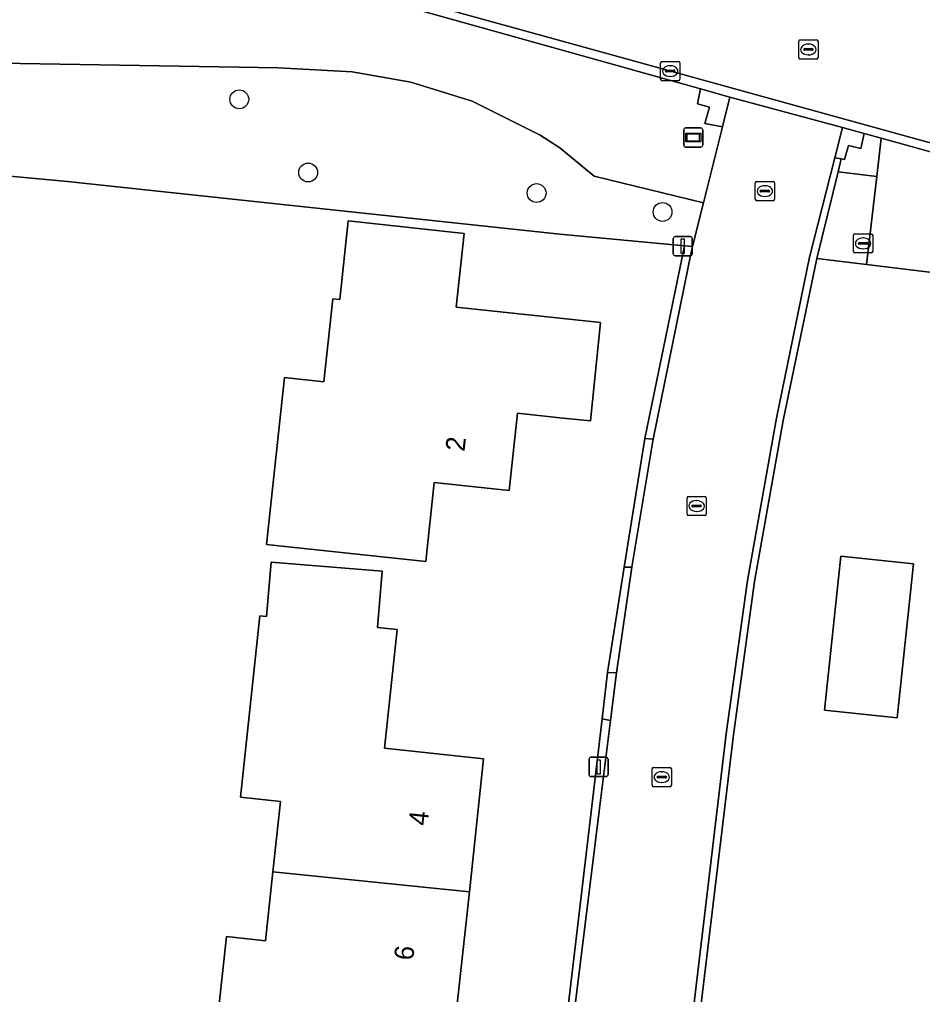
# Model space of a CAD drawing. Extents: x 162156 to 163172, y 378995 to 380779.
# Drawn here: x 162471.9 to 162518.8, y 380585.7 to 380636.4 of the extents above; entities that cross this region are included whole.
import ezdxf

# ---------------------------------------------------------------- set-up
doc = ezdxf.new("R2010")
doc.units = 0
for name, color, linetype in [('IMGEO_Boom', 7, 'Continuous'), ('IMGEO_Brandkraan', 7, 'Continuous'), ('IMGEO_Erf', 7, 'Continuous'), ('IMGEO_Groenvoorziening', 7, 'Continuous'), ('IMGEO_Kolk', 7, 'Continuous'), ('IMGEO_Lichtmast', 7, 'Continuous'), ('IMGEO_Pand', 7, 'Continuous'), ('IMGEO_Pand_nummerreeks', 7, 'Continuous'), ('IMGEO_Rijbaan_lokaal_gesloten', 7, 'Continuous'), ('IMGEO_Rijbaan_lokaal_open', 7, 'Continuous'), ('IMGEO_Rioolput', 7, 'Continuous'), ('IMGEO_Straatnaambord', 7, 'Continuous'), ('IMGEO_Voetpad_open', 7, 'Continuous')]:
    doc.layers.add(name, color=color, linetype=linetype)

msp = doc.modelspace()

# ---------------------------------------------------------------- linework, layer by layer
at = {"layer": 'IMGEO_Boom'}
for centre in [(162483.344, 380632.211), (162486.919, 380628.409), (162498.79, 380627.343), (162505.335, 380626.359)]:
    msp.add_circle(centre, 0.489, dxfattribs=at)
at = {"layer": 'IMGEO_Brandkraan'}
for p, q in [((162515.325, 380625.227), (162516.177, 380625.227)), ((162515.25, 380624.301), (162515.25, 380625.153)), ((162515.509, 380624.721), (162515.509, 380624.733)), ((162515.552, 380624.77), (162515.95, 380624.77)), ((162515.738, 380625.007), (162515.763, 380625.007)), ((162515.993, 380624.733), (162515.993, 380624.721)), ((162516.251, 380625.153), (162516.251, 380624.301)), ((162516.177, 380624.227), (162515.325, 380624.227)), ((162515.947, 380624.684), (162515.549, 380624.684)), ((162515.761, 380624.447), (162515.736, 380624.447))]:
    msp.add_line(p, q, dxfattribs=at)
for points in [[(162515.325, 380625.227), (162516.177, 380625.227)], [(162515.25, 380624.301), (162515.25, 380625.153)], [(162516.251, 380625.153), (162516.251, 380624.301)], [(162516.177, 380624.227), (162515.325, 380624.227)]]:
    msp.add_lwpolyline(points, dxfattribs=at)
for centre, radius, start, end in [((162515.327, 380625.151), 0.0765, 91.552, 178.448), ((162515.327, 380625.151), 0.0765, 91.552, 178.448), ((162516.175, 380625.151), 0.0765, 1.552, 88.448), ((162516.175, 380625.151), 0.0765, 1.552, 88.448), ((162515.549, 380624.73), 0.0403, 85.8775, 175.7526), ((162515.546, 380624.72), 0.0366, 178.938, 274.7102), ((162515.95, 380624.727), 0.043, 264.8664, 352.4533), ((162515.954, 380624.732), 0.0386, 1.7309, 96.639), ((162515.327, 380624.303), 0.0765, 181.552, 268.448), ((162515.327, 380624.303), 0.0765, 181.552, 268.448), ((162516.175, 380624.303), 0.0765, 271.552, 358.448), ((162516.175, 380624.303), 0.0765, 271.552, 358.448)]:
    msp.add_arc(centre, radius, start, end, dxfattribs=at)
for centre, major_axis, ratio, start_param, end_param in [((162515.737, 380624.727), (-0.387, 0.002), 0.722429, 4.712389, 7.853982), ((162515.762, 380624.727), (-0.39, 0.002), 0.717154, 1.570796, 4.712389)]:
    msp.add_ellipse(centre, major_axis=major_axis, ratio=ratio, start_param=start_param, end_param=end_param, dxfattribs=at)
at = {"layer": 'IMGEO_Erf'}
for points in [[(162502.189, 380600.029), (162502.472, 380602.43), (162503.344, 380607.897), (162504.412, 380614.587), (162506.479, 380624.601), (162500, 380625.199), (162474.413, 380627.947), (162438.013, 380631.313), (162439.468, 380615.71), (162440.015, 380601.307), (162439.768, 380588.845), (162437.05, 380560.078), (162436.315, 380552.915), (162465.464, 380549.639), (162490.566, 380547.063), (162491.852, 380559.491), (162500, 380564.632), (162501.13, 380565.345), (162499.992, 380567.526)], [(162613.014, 380601.728), (162588.761, 380608.641), (162562.907, 380615.723), (162561.588, 380616.076), (162561.281, 380614.93), (162560.907, 380613.778), (162560.551, 380612.977), (162560.107, 380612.313), (162544.999, 380616.712), (162537.976, 380618.182), (162519.769, 380623.159), (162515.938, 380623.63), (162513.343, 380623.949), (162511.606, 380615.531), (162510.109, 380607.162), (162509.012, 380599.183), (162505.8, 380572.406)], [(162499.104, 380574.108), (162499.208, 380574.957), (162499.508, 380577.409), (162499.584, 380578.026), (162500, 380581.422), (162502.189, 380600.029)]]:
    msp.add_lwpolyline(points, dxfattribs=at)
for points in [[(162485.685, 380617.752), (162487.743, 380617.531), (162488.208, 380621.852), (162488.56, 380621.814), (162489, 380625.896), (162495.03, 380625.247), (162494.616, 380621.403), (162500, 380620.836), (162502.118, 380620.613), (162501.586, 380615.506), (162500, 380615.669), (162497.794, 380615.896), (162497.362, 380611.883), (162493.475, 380612.302), (162493.033, 380608.196), (162484.752, 380609.088)], [(162481.674, 380579.453), (162482.671, 380588.712), (162484.697, 380588.494), (162485.082, 380592.069), (162485.476, 380595.729), (162483.408, 380595.952), (162484.419, 380605.366), (162484.765, 380605.338), (162484.995, 380608.169), (162490.766, 380607.701), (162490.528, 380604.766), (162491.55, 380604.656), (162490.887, 380598.495), (162496.039, 380597.94), (162495.295, 380591.027), (162494.532, 380583.945), (162489.336, 380584.504), (162488.71, 380578.696), (162488.27, 380574.611), (162481.234, 380575.368)], [(162517.515, 380600.073), (162513.752, 380600.472), (162514.6, 380608.468), (162518.363, 380608.069)]]:
    msp.add_lwpolyline(points, close=True, dxfattribs=at)
at = {"layer": 'IMGEO_Groenvoorziening'}
msp.add_lwpolyline([(162465.547, 380639.847), (162452.609, 380638.519), (162438.317, 380637.334), (162438.521, 380635.944), (162437.595, 380635.83), (162437.854, 380633.025), (162463.991, 380631.774), (162466.779, 380634.155), (162485.377, 380633.853), (162489.211, 380633.646), (162492.259, 380633.107), (162495.434, 380632.111), (162498.979, 380630.341), (162500, 380629.686), (162501.777, 380628.214), (162507.464, 380626.838), (162508.449, 380630.789), (162507.522, 380630.962), (162507.766, 380631.808), (162507.151, 380631.978), (162507.306, 380632.754), (162500, 380634.796), (162491.138, 380637.273)], dxfattribs=at)
for points in [[(162507.464, 380626.838), (162501.777, 380628.214), (162500, 380629.686), (162498.979, 380630.341), (162495.434, 380632.111), (162492.259, 380633.107), (162489.211, 380633.646), (162485.377, 380633.853), (162466.779, 380634.155), (162463.991, 380631.774), (162437.854, 380633.025), (162438.013, 380631.313), (162474.413, 380627.947), (162500, 380625.199), (162506.479, 380624.601), (162506.896, 380624.563)], [(162516.692, 380630.19), (162515.816, 380630.433), (162515.633, 380629.66), (162514.99, 380629.805), (162514.784, 380629.087), (162514.62, 380629.116), (162514.451, 380628.435), (162516.464, 380628.204)], [(162515.938, 380623.63), (162516.464, 380628.204), (162514.451, 380628.435), (162513.343, 380623.949)]]:
    msp.add_lwpolyline(points, close=True, dxfattribs=at)
at = {"layer": 'IMGEO_Kolk'}
for p, q in [((162505.233, 380633.253), (162505.233, 380634.105)), ((162505.308, 380634.179), (162506.16, 380634.179)), ((162505.721, 380633.959), (162505.746, 380633.959)), ((162506.234, 380634.105), (162506.234, 380633.253)), ((162505.492, 380633.673), (162505.492, 380633.685)), ((162505.93, 380633.636), (162505.532, 380633.636)), ((162505.535, 380633.722), (162505.933, 380633.722)), ((162505.744, 380633.399), (162505.719, 380633.399)), ((162505.976, 380633.685), (162505.976, 380633.673)), ((162506.16, 380633.179), (162505.308, 380633.179)), ((162510.149, 380627.016), (162510.149, 380627.868)), ((162510.224, 380627.942), (162511.076, 380627.942)), ((162511.15, 380627.868), (162511.15, 380627.016)), ((162510.408, 380627.436), (162510.408, 380627.448)), ((162510.846, 380627.399), (162510.448, 380627.399)), ((162510.451, 380627.485), (162510.849, 380627.485)), ((162510.637, 380627.722), (162510.662, 380627.722)), ((162510.892, 380627.448), (162510.892, 380627.436)), ((162511.076, 380626.942), (162510.224, 380626.942)), ((162510.66, 380627.162), (162510.635, 380627.162)), ((162506.679, 380611.58), (162507.531, 380611.58)), ((162506.604, 380610.654), (162506.604, 380611.506)), ((162506.863, 380611.074), (162506.863, 380611.086)), ((162507.301, 380611.037), (162506.903, 380611.037)), ((162506.906, 380611.123), (162507.304, 380611.123)), ((162507.092, 380611.36), (162507.117, 380611.36)), ((162507.347, 380611.086), (162507.347, 380611.074)), ((162507.605, 380611.506), (162507.605, 380610.654)), ((162507.531, 380610.58), (162506.679, 380610.58)), ((162507.115, 380610.8), (162507.09, 380610.8)), ((162504.792, 380596.567), (162504.792, 380597.419)), ((162504.867, 380597.493), (162505.719, 380597.493)), ((162505.793, 380597.419), (162505.793, 380596.567)), ((162505.051, 380596.987), (162505.051, 380596.999)), ((162505.489, 380596.95), (162505.091, 380596.95)), ((162505.094, 380597.036), (162505.492, 380597.036)), ((162505.28, 380597.273), (162505.305, 380597.273)), ((162505.535, 380596.999), (162505.535, 380596.987)), ((162505.719, 380596.493), (162504.867, 380596.493)), ((162505.303, 380596.713), (162505.278, 380596.713))]:
    msp.add_line(p, q, dxfattribs=at)
for points in [[(162505.233, 380633.253), (162505.233, 380634.105)], [(162505.308, 380634.179), (162506.16, 380634.179)], [(162506.234, 380634.105), (162506.234, 380633.253)], [(162506.16, 380633.179), (162505.308, 380633.179)], [(162510.149, 380627.016), (162510.149, 380627.868)], [(162510.224, 380627.942), (162511.076, 380627.942)], [(162511.15, 380627.868), (162511.15, 380627.016)], [(162511.076, 380626.942), (162510.224, 380626.942)], [(162506.679, 380611.58), (162507.531, 380611.58)], [(162506.604, 380610.654), (162506.604, 380611.506)], [(162507.605, 380611.506), (162507.605, 380610.654)], [(162507.531, 380610.58), (162506.679, 380610.58)], [(162504.792, 380596.567), (162504.792, 380597.419)], [(162504.867, 380597.493), (162505.719, 380597.493)], [(162505.793, 380597.419), (162505.793, 380596.567)], [(162505.719, 380596.493), (162504.867, 380596.493)]]:
    msp.add_lwpolyline(points, dxfattribs=at)
for centre, radius, start, end in [((162505.31, 380634.103), 0.0765, 91.552, 178.448), ((162505.31, 380634.103), 0.0765, 91.552, 178.448), ((162506.158, 380634.103), 0.0765, 1.552, 88.448), ((162506.158, 380634.103), 0.0765, 1.552, 88.448), ((162505.532, 380633.682), 0.0403, 85.8775, 175.7526), ((162505.529, 380633.672), 0.0366, 178.938, 274.7102), ((162505.933, 380633.679), 0.043, 264.8664, 352.4533), ((162505.937, 380633.684), 0.0386, 1.7309, 96.639), ((162505.31, 380633.255), 0.0765, 181.552, 268.448), ((162505.31, 380633.255), 0.0765, 181.552, 268.448), ((162506.158, 380633.255), 0.0765, 271.552, 358.448), ((162506.158, 380633.255), 0.0765, 271.552, 358.448), ((162510.226, 380627.866), 0.0765, 91.552, 178.448), ((162510.226, 380627.866), 0.0765, 91.552, 178.448), ((162511.074, 380627.866), 0.0765, 1.552, 88.448), ((162511.074, 380627.866), 0.0765, 1.552, 88.448), ((162510.448, 380627.445), 0.0403, 85.8775, 175.7526), ((162510.445, 380627.435), 0.0366, 178.938, 274.7102), ((162510.849, 380627.442), 0.043, 264.8664, 352.4533), ((162510.853, 380627.447), 0.0386, 1.7309, 96.639), ((162510.226, 380627.018), 0.0765, 181.552, 268.448), ((162510.226, 380627.018), 0.0765, 181.552, 268.448), ((162511.074, 380627.018), 0.0765, 271.552, 358.448), ((162511.074, 380627.018), 0.0765, 271.552, 358.448), ((162506.681, 380611.504), 0.0765, 91.552, 178.448), ((162506.681, 380611.504), 0.0765, 91.552, 178.448), ((162507.529, 380611.504), 0.0765, 1.552, 88.448), ((162507.529, 380611.504), 0.0765, 1.552, 88.448), ((162506.903, 380611.083), 0.0403, 85.8775, 175.7526), ((162506.9, 380611.073), 0.0366, 178.938, 274.7102), ((162507.304, 380611.08), 0.043, 264.8664, 352.4533), ((162507.308, 380611.085), 0.0386, 1.7309, 96.639), ((162506.681, 380610.656), 0.0765, 181.552, 268.448), ((162506.681, 380610.656), 0.0765, 181.552, 268.448), ((162507.529, 380610.656), 0.0765, 271.552, 358.448), ((162507.529, 380610.656), 0.0765, 271.552, 358.448), ((162504.869, 380597.417), 0.0765, 91.552, 178.448), ((162504.869, 380597.417), 0.0765, 91.552, 178.448), ((162505.717, 380597.417), 0.0765, 1.552, 88.448), ((162505.717, 380597.417), 0.0765, 1.552, 88.448), ((162505.091, 380596.996), 0.0403, 85.8775, 175.7526), ((162505.088, 380596.986), 0.0366, 178.938, 274.7102), ((162505.492, 380596.993), 0.043, 264.8664, 352.4533), ((162505.496, 380596.998), 0.0386, 1.7309, 96.639), ((162504.869, 380596.569), 0.0765, 181.552, 268.448), ((162504.869, 380596.569), 0.0765, 181.552, 268.448), ((162505.717, 380596.569), 0.0765, 271.552, 358.448), ((162505.717, 380596.569), 0.0765, 271.552, 358.448)]:
    msp.add_arc(centre, radius, start, end, dxfattribs=at)
for centre, major_axis, ratio, start_param, end_param in [((162505.72, 380633.679), (-0.387, 0.002), 0.722429, 4.712389, 7.853982), ((162505.745, 380633.679), (-0.39, 0.002), 0.717154, 1.570796, 4.712389), ((162510.636, 380627.442), (-0.387, 0.002), 0.722429, 4.712389, 7.853982), ((162510.661, 380627.442), (-0.39, 0.002), 0.717154, 1.570796, 4.712389), ((162507.091, 380611.08), (-0.387, 0.002), 0.722429, 4.712389, 7.853982), ((162507.116, 380611.08), (-0.39, 0.002), 0.717154, 1.570796, 4.712389), ((162505.279, 380596.993), (-0.387, 0.002), 0.722429, 4.712389, 7.853982), ((162505.304, 380596.993), (-0.39, 0.002), 0.717154, 1.570796, 4.712389)]:
    msp.add_ellipse(centre, major_axis=major_axis, ratio=ratio, start_param=start_param, end_param=end_param, dxfattribs=at)
at = {"layer": 'IMGEO_Lichtmast'}
for p, q in [((162505.888, 380624.18), (162505.888, 380624.98)), ((162505.888, 380624.98), (162505.888, 380624.18)), ((162505.988, 380625.08), (162506.778, 380625.08)), ((162506.778, 380625.08), (162505.988, 380625.08)), ((162506.878, 380624.98), (162506.878, 380624.18)), ((162506.878, 380624.18), (162506.878, 380624.98)), ((162506.778, 380624.08), (162505.988, 380624.08)), ((162505.988, 380624.08), (162506.778, 380624.08)), ((162501.514, 380597.123), (162501.514, 380597.923)), ((162501.514, 380597.923), (162501.514, 380597.123)), ((162501.614, 380598.023), (162502.404, 380598.023)), ((162502.404, 380598.023), (162501.614, 380598.023)), ((162502.504, 380597.923), (162502.504, 380597.123)), ((162502.504, 380597.123), (162502.504, 380597.923)), ((162502.404, 380597.023), (162501.614, 380597.023)), ((162501.614, 380597.023), (162502.404, 380597.023))]:
    msp.add_line(p, q, dxfattribs=at)
for points in [[(162506.308, 380624.955), (162506.458, 380624.955), (162506.458, 380624.205), (162506.308, 380624.205), (162506.308, 380624.955)], [(162501.934, 380597.898), (162502.084, 380597.898), (162502.084, 380597.148), (162501.934, 380597.148), (162501.934, 380597.898)]]:
    msp.add_lwpolyline(points, dxfattribs=at)
for centre, start, end in [((162505.988, 380624.98), 90, 180), ((162505.988, 380624.98), 90, 180), ((162506.778, 380624.98), 0, 90), ((162506.778, 380624.98), 360, 90), ((162505.988, 380624.18), 180, 270), ((162505.988, 380624.18), 180, 270), ((162506.778, 380624.18), 270, 0), ((162506.778, 380624.18), 270, 0), ((162501.614, 380597.923), 90, 180), ((162501.614, 380597.923), 90, 180), ((162502.404, 380597.923), 0, 90), ((162502.404, 380597.923), 360, 90), ((162501.614, 380597.123), 180, 270), ((162501.614, 380597.123), 180, 270), ((162502.404, 380597.123), 270, 0), ((162502.404, 380597.123), 270, 0)]:
    msp.add_arc(centre, 0.1, start, end, dxfattribs=at)
at = {"layer": 'IMGEO_Pand'}
for points in [[(162493.033, 380608.196), (162493.475, 380612.302), (162497.362, 380611.883), (162497.794, 380615.896), (162500, 380615.669), (162501.586, 380615.506), (162502.118, 380620.613), (162500, 380620.836), (162494.616, 380621.403), (162495.03, 380625.247), (162489, 380625.896), (162488.56, 380621.814), (162488.208, 380621.852), (162487.743, 380617.531), (162485.685, 380617.752), (162484.752, 380609.088)], [(162496.039, 380597.94), (162490.887, 380598.495), (162491.55, 380604.656), (162490.528, 380604.766), (162490.766, 380607.701), (162484.995, 380608.169), (162484.765, 380605.338), (162484.419, 380605.366), (162483.408, 380595.952), (162485.476, 380595.729), (162485.082, 380592.069), (162495.295, 380591.027)], [(162517.515, 380600.073), (162518.363, 380608.069), (162514.6, 380608.468), (162513.752, 380600.472)], [(162488.71, 380578.696), (162489.336, 380584.504), (162494.532, 380583.945), (162495.295, 380591.027), (162485.082, 380592.069), (162484.697, 380588.494), (162482.671, 380588.712), (162481.674, 380579.453), (162482.144, 380579.402)]]:
    msp.add_lwpolyline(points, close=True, dxfattribs=at)
at = {"layer": 'IMGEO_Rijbaan_lokaal_gesloten'}
for points in [[(162477.228, 380639.674), (162480.976, 380639.284), (162491.138, 380637.273), (162500, 380634.796), (162507.306, 380632.754), (162508.833, 380632.327), (162514.682, 380630.745), (162515.001, 380630.659), (162515.816, 380630.433), (162516.692, 380630.19), (162520.317, 380629.183), (162520.472, 380629.14), (162539.243, 380623.93), (162546.179, 380622.005), (162562.034, 380617.74), (162563.328, 380617.392), (162567.697, 380616.172), (162569.642, 380615.628), (162574.005, 380614.41), (162591.403, 380609.551), (162600.159, 380607.105), (162600.248, 380607.426)], [(162493.395, 380637.088), (162500, 380635.264), (162520.438, 380629.619), (162522.044, 380629.176), (162547.05, 380622.206), (162600.248, 380607.426), (162612.155, 380604.118)], [(162600.248, 380607.426), (162547.05, 380622.206), (162522.044, 380629.176), (162520.438, 380629.619), (162500, 380635.264), (162493.395, 380637.088)]]:
    msp.add_lwpolyline(points, dxfattribs=at)
at = {"layer": 'IMGEO_Rijbaan_lokaal_open'}
for points in [[(162505.493, 380572.753), (162508.646, 380599.247), (162509.739, 380607.207), (162511.252, 380615.648), (162512.967, 380624.014), (162514.282, 380629.177), (162514.682, 380630.745), (162508.833, 380632.327), (162508.449, 380630.789), (162507.464, 380626.838), (162506.896, 380624.563), (162506.861, 380624.423), (162504.841, 380614.547), (162503.735, 380607.908), (162502.934, 380602.411), (162502.624, 380599.941), (162502.032, 380595.226), (162500.328, 380581.389), (162500, 380578.214), (162499.979, 380578.011), (162499.909, 380577.331), (162499.667, 380574.99)], [(162513.343, 380623.949), (162514.451, 380628.435), (162514.62, 380629.116), (162514.282, 380629.177), (162512.967, 380624.014), (162511.252, 380615.648), (162509.739, 380607.207), (162508.646, 380599.247), (162505.493, 380572.753)], [(162505.8, 380572.406), (162509.012, 380599.183), (162510.109, 380607.162), (162511.606, 380615.531), (162513.343, 380623.949)]]:
    msp.add_lwpolyline(points, dxfattribs=at)
for points in [[(162508.833, 380632.327), (162507.306, 380632.754), (162507.151, 380631.978), (162507.766, 380631.808), (162507.522, 380630.962), (162508.449, 380630.789)], [(162515.816, 380630.433), (162515.001, 380630.659), (162514.682, 380630.745), (162514.282, 380629.177), (162514.62, 380629.116), (162514.784, 380629.087), (162514.99, 380629.805), (162515.633, 380629.66)], [(162506.896, 380624.563), (162506.479, 380624.601), (162504.412, 380614.587), (162504.841, 380614.547), (162506.861, 380624.423)], [(162503.344, 380607.897), (162502.472, 380602.43), (162502.934, 380602.411), (162503.735, 380607.908)], [(162500, 380581.422), (162500.328, 380581.389), (162502.032, 380595.226), (162502.624, 380599.941), (162502.189, 380600.029)]]:
    msp.add_lwpolyline(points, close=True, dxfattribs=at)
at = {"layer": 'IMGEO_Rioolput'}
for p, q in [((162512.409, 380634.376), (162512.409, 380635.228)), ((162512.484, 380635.302), (162513.336, 380635.302)), ((162512.711, 380634.845), (162513.109, 380634.845)), ((162512.897, 380635.082), (162512.922, 380635.082)), ((162513.41, 380635.228), (162513.41, 380634.376)), ((162512.668, 380634.796), (162512.668, 380634.808)), ((162513.106, 380634.759), (162512.708, 380634.759)), ((162512.92, 380634.522), (162512.895, 380634.522)), ((162513.152, 380634.808), (162513.152, 380634.796)), ((162513.336, 380634.302), (162512.484, 380634.302))]:
    msp.add_line(p, q, dxfattribs=at)
for points in [[(162512.409, 380634.376), (162512.409, 380635.228)], [(162512.484, 380635.302), (162513.336, 380635.302)], [(162513.41, 380635.228), (162513.41, 380634.376)], [(162513.336, 380634.302), (162512.484, 380634.302)]]:
    msp.add_lwpolyline(points, dxfattribs=at)
for centre, radius, start, end in [((162512.486, 380635.226), 0.0765, 91.552, 178.448), ((162512.486, 380635.226), 0.0765, 91.552, 178.448), ((162512.708, 380634.805), 0.0403, 85.8775, 175.7526), ((162513.113, 380634.807), 0.0386, 1.7309, 96.639), ((162513.334, 380635.226), 0.0765, 1.552, 88.448), ((162513.334, 380635.226), 0.0765, 1.552, 88.448), ((162512.486, 380634.378), 0.0765, 181.552, 268.448), ((162512.486, 380634.378), 0.0765, 181.552, 268.448), ((162512.705, 380634.795), 0.0366, 178.938, 274.7102), ((162513.109, 380634.802), 0.043, 264.8664, 352.4533), ((162513.334, 380634.378), 0.0765, 271.552, 358.448), ((162513.334, 380634.378), 0.0765, 271.552, 358.448)]:
    msp.add_arc(centre, radius, start, end, dxfattribs=at)
for centre, major_axis, ratio, start_param, end_param in [((162512.896, 380634.802), (-0.387, 0.002), 0.722429, 4.712389, 7.853982), ((162512.921, 380634.802), (-0.39, 0.002), 0.717154, 1.570796, 4.712389)]:
    msp.add_ellipse(centre, major_axis=major_axis, ratio=ratio, start_param=start_param, end_param=end_param, dxfattribs=at)
at = {"layer": 'IMGEO_Straatnaambord'}
for p, q in [((162506.434, 380629.828), (162506.434, 380630.628)), ((162506.434, 380630.628), (162506.434, 380629.828)), ((162506.534, 380630.728), (162507.324, 380630.728)), ((162507.324, 380630.728), (162506.534, 380630.728)), ((162507.424, 380630.628), (162507.424, 380629.828)), ((162507.424, 380629.828), (162507.424, 380630.628)), ((162507.324, 380629.728), (162506.534, 380629.728)), ((162506.534, 380629.728), (162507.324, 380629.728))]:
    msp.add_line(p, q, dxfattribs=at)
for points in [[(162506.535, 380630.46), (162507.323, 380630.46), (162507.323, 380629.996), (162506.535, 380629.996), (162506.535, 380630.46)], [(162506.6, 380630.395), (162506.6, 380630.061), (162507.258, 380630.061), (162507.258, 380630.395), (162506.6, 380630.395)]]:
    msp.add_lwpolyline(points, dxfattribs=at)
for centre, start, end in [((162506.534, 380630.628), 90, 180), ((162506.534, 380630.628), 90, 180), ((162507.324, 380630.628), 0, 90), ((162507.324, 380630.628), 360, 90), ((162506.534, 380629.828), 180, 270), ((162506.534, 380629.828), 180, 270), ((162507.324, 380629.828), 270, 0), ((162507.324, 380629.828), 270, 0)]:
    msp.add_arc(centre, 0.1, start, end, dxfattribs=at)
at = {"layer": 'IMGEO_Voetpad_open'}
for points in [[(162519.769, 380623.159), (162520.266, 380627.386), (162520.472, 380629.14), (162520.317, 380629.183), (162516.692, 380630.19), (162516.464, 380628.204), (162515.938, 380623.63)], [(162504.841, 380614.547), (162504.412, 380614.587), (162503.344, 380607.897), (162503.735, 380607.908)], [(162502.624, 380599.941), (162502.934, 380602.411), (162502.472, 380602.43), (162502.189, 380600.029)]]:
    msp.add_lwpolyline(points, close=True, dxfattribs=at)

# ---------------------------------------------------------------- texts
at = {"layer": 'IMGEO_Pand_nummerreeks'}
for s, rotation, p in [('2', 83.8558, (162495.043, 380613.883)), ('4', 83.8524, (162493.127, 380594.437)), ('6', 83.854, (162492.373, 380587.439))]:
    msp.add_text(s, height=1, rotation=rotation, dxfattribs=at).set_placement(p)

doc.saveas('drawing.dxf')
